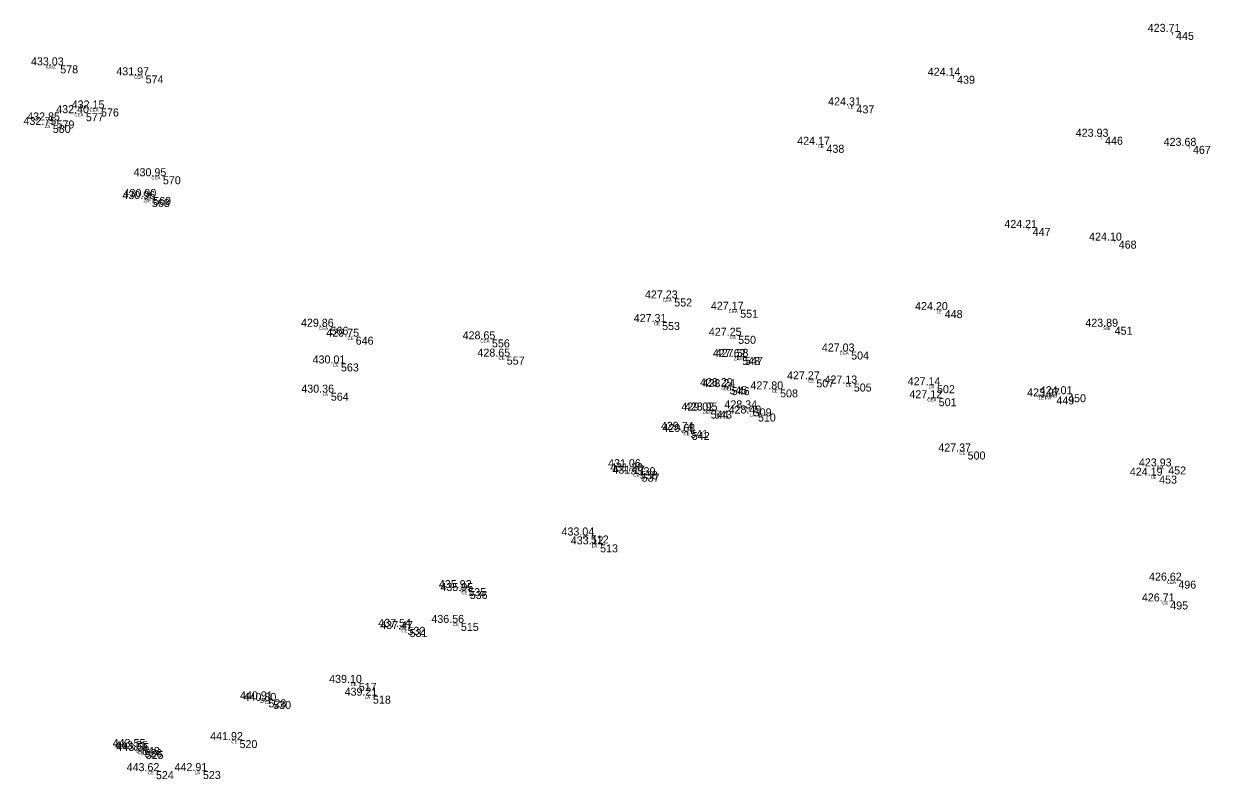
# Model space of a CAD drawing. Extents: x -639373 to -639057, y -1138651 to -1138359.
# Drawn here: x -639295.4 to -639184.2, y -1138643.1 to -1138572.3 of the extents above; entities that cross this region are included whole.
import ezdxf

# ---------------------------------------------------------------- set-up
doc = ezdxf.new("R2010")
doc.units = 0
for name, color, linetype in [('Vrstva 11', 7, 'Continuous'), ('Vrstva 12', 7, 'Continuous'), ('Vrstva 13', 7, 'Continuous'), ('Vrstva 14', 7, 'Continuous'), ('Vrstva 57', 7, 'Continuous')]:
    doc.layers.add(name, color=color, linetype=linetype)

msp = doc.modelspace()

# ---------------------------------------------------------------- linework, layer by layer
at = {"layer": 'Vrstva 11'}
for p, q in [((-639187.67, -1138573.11), (-639187.67, -1138573.11)), ((-639292.26, -1138576.25), (-639292.26, -1138576.25)), ((-639284.26, -1138577.18), (-639284.26, -1138577.18)), ((-639208.2, -1138577.22), (-639208.2, -1138577.22)), ((-639217.63, -1138580), (-639217.63, -1138580)), ((-639289.86, -1138580.73), (-639289.86, -1138580.73)), ((-639288.44, -1138580.29), (-639288.44, -1138580.29)), ((-639292.96, -1138581.83), (-639292.96, -1138581.83)), ((-639292.61, -1138581.41), (-639292.61, -1138581.41)), ((-639194.33, -1138582.94), (-639194.33, -1138582.94)), ((-639220.44, -1138583.69), (-639220.44, -1138583.69)), ((-639186.09, -1138583.79), (-639186.09, -1138583.79)), ((-639282.64, -1138586.64), (-639282.64, -1138586.64)), ((-639283.67, -1138588.77), (-639283.67, -1138588.77)), ((-639283.55, -1138588.58), (-639283.55, -1138588.58)), ((-639201.11, -1138591.48), (-639201.11, -1138591.48)), ((-639193.05, -1138592.67), (-639193.05, -1138592.67)), ((-639234.71, -1138598.09), (-639234.71, -1138598.09)), ((-639228.53, -1138599.15), (-639228.53, -1138599.15)), ((-639209.36, -1138599.18), (-639209.36, -1138599.18)), ((-639266.93, -1138600.74), (-639266.93, -1138600.74)), ((-639235.85, -1138600.3), (-639235.85, -1138600.3)), ((-639193.43, -1138600.74), (-639193.43, -1138600.74)), ((-639264.57, -1138601.67), (-639264.57, -1138601.67)), ((-639251.8, -1138601.92), (-639251.8, -1138601.92)), ((-639228.72, -1138601.59), (-639228.72, -1138601.59)), ((-639218.13, -1138603.06), (-639218.13, -1138603.06)), ((-639265.95, -1138604.18), (-639265.95, -1138604.18)), ((-639250.41, -1138603.54), (-639250.41, -1138603.54)), ((-639228.34, -1138603.58), (-639228.34, -1138603.58)), ((-639228.08, -1138603.56), (-639228.08, -1138603.56)), ((-639221.39, -1138605.67), (-639221.39, -1138605.67)), ((-639229.54, -1138606.31), (-639229.54, -1138606.31)), ((-639229.32, -1138606.4), (-639229.32, -1138606.4)), ((-639224.79, -1138606.61), (-639224.79, -1138606.61)), ((-639217.88, -1138606.06), (-639217.88, -1138606.06)), ((-639210.08, -1138606.22), (-639210.08, -1138606.22)), ((-639266.9, -1138606.92), (-639266.9, -1138606.92)), ((-639209.92, -1138607.44), (-639209.92, -1138607.44)), ((-639198.89, -1138607.27), (-639198.89, -1138607.27)), ((-639197.79, -1138607.06), (-639197.79, -1138607.06)), ((-639231.29, -1138608.59), (-639231.29, -1138608.59)), ((-639230.97, -1138608.59), (-639230.97, -1138608.59)), ((-639227.26, -1138608.39), (-639227.26, -1138608.39)), ((-639226.87, -1138608.87), (-639226.87, -1138608.87)), ((-639233.21, -1138610.4), (-639233.21, -1138610.4)), ((-639233.07, -1138610.6), (-639233.07, -1138610.6)), ((-639207.21, -1138612.43), (-639207.21, -1138612.43)), ((-639238.14, -1138613.9), (-639238.14, -1138613.9)), ((-639237.93, -1138614.28), (-639237.93, -1138614.28)), ((-639237.77, -1138614.51), (-639237.77, -1138614.51)), ((-639188.41, -1138613.83), (-639188.41, -1138613.83)), ((-639189.26, -1138614.69), (-639189.26, -1138614.69)), ((-639242.53, -1138620.3), (-639242.53, -1138620.3)), ((-639241.66, -1138621.13), (-639241.66, -1138621.13)), ((-639187.46, -1138624.53), (-639187.46, -1138624.53)), ((-639254.02, -1138625.23), (-639254.02, -1138625.23)), ((-639253.88, -1138625.5), (-639253.88, -1138625.5)), ((-639188.22, -1138626.48), (-639188.22, -1138626.48)), ((-639259.71, -1138628.86), (-639259.71, -1138628.86)), ((-639259.52, -1138629.07), (-639259.52, -1138629.07)), ((-639254.71, -1138628.49), (-639254.71, -1138628.49)), ((-639264.28, -1138634.11), (-639264.28, -1138634.11)), ((-639272.75, -1138635.65), (-639272.75, -1138635.65)), ((-639262.95, -1138635.31), (-639262.95, -1138635.31)), ((-639272.3, -1138635.8), (-639272.3, -1138635.8)), ((-639284.6, -1138640.12), (-639284.6, -1138640.12)), ((-639275.46, -1138639.47), (-639275.46, -1138639.47)), ((-639284.38, -1138640.33), (-639284.38, -1138640.33)), ((-639284.25, -1138640.49), (-639284.25, -1138640.49)), ((-639283.29, -1138642.38), (-639283.29, -1138642.38)), ((-639278.89, -1138642.37), (-639278.89, -1138642.37))]:
    msp.add_line(p, q, dxfattribs=at)

# ---------------------------------------------------------------- texts
at = {"layer": 'Vrstva 12'}
for s, p in [('433.03 ', (-639294.73, -1138576.25)), ('431.97 ', (-639286.73, -1138577.18)), ('432.40 ', (-639292.36, -1138580.73)), ('432.15 ', (-639290.91, -1138580.29)), ('432.75 ', (-639295.43, -1138581.83)), ('432.85 ', (-639295.08, -1138581.41)), ('430.95 ', (-639285.11, -1138586.64)), ('430.90 ', (-639286.05, -1138588.58)), ('430.96 ', (-639286.16, -1138588.77)), ('427.23 ', (-639237.18, -1138598.09)), ('427.17 ', (-639231, -1138599.15)), ('429.86 ', (-639269.42, -1138600.74)), ('427.31 ', (-639238.23, -1138600.3)), ('429.75 ', (-639267.04, -1138601.67)), ('428.65 ', (-639254.27, -1138601.92)), ('427.25 ', (-639231.19, -1138601.59)), ('427.03 ', (-639220.6, -1138603.06)), ('430.01 ', (-639268.33, -1138604.18)), ('428.65 ', (-639252.88, -1138603.54)), ('427.62 ', (-639230.81, -1138603.58)), ('427.58 ', (-639230.55, -1138603.56)), ('428.29 ', (-639232.01, -1138606.31)), ('428.24 ', (-639231.79, -1138606.4)), ('427.27 ', (-639223.86, -1138605.67)), ('427.13 ', (-639220.35, -1138606.06)), ('427.14 ', (-639212.55, -1138606.22)), ('430.36 ', (-639269.39, -1138606.92)), ('427.80 ', (-639227.29, -1138606.61)), ('427.12 ', (-639212.39, -1138607.44)), ('423.97 ', (-639201.36, -1138607.27)), ('424.01 ', (-639200.17, -1138607.06)), ('429.02 ', (-639233.76, -1138608.59)), ('428.95 ', (-639233.44, -1138608.59)), ('428.34 ', (-639229.73, -1138608.39)), ('428.49 ', (-639229.34, -1138608.87)), ('429.74 ', (-639235.68, -1138610.4)), ('429.68 ', (-639235.54, -1138610.6)), ('427.37 ', (-639209.68, -1138612.43)), ('431.06 ', (-639240.63, -1138613.9)), ('431.20 ', (-639240.43, -1138614.28)), ('423.93 ', (-639190.88, -1138613.83)), ('431.17 ', (-639240.24, -1138614.51)), ('424.19 ', (-639191.73, -1138614.69)), ('433.04 ', (-639245, -1138620.3)), ('433.12 ', (-639244.13, -1138621.13)), ('435.92 ', (-639256.49, -1138625.23)), ('426.62 ', (-639189.93, -1138624.53)), ('435.95 ', (-639256.35, -1138625.5)), ('426.71 ', (-639190.6, -1138626.48)), ('436.56 ', (-639257.2, -1138628.49)), ('437.54 ', (-639262.18, -1138628.86)), ('437.47 ', (-639261.99, -1138629.07)), ('439.10 ', (-639266.78, -1138634.11)), ('439.21 ', (-639265.33, -1138635.31)), ('440.91 ', (-639275.13, -1138635.65)), ('440.80 ', (-639274.8, -1138635.8)), ('441.92 ', (-639277.93, -1138639.47)), ('443.55 ', (-639287.07, -1138640.12)), ('443.55 ', (-639286.85, -1138640.33)), ('443.55 ', (-639286.72, -1138640.49)), ('443.62 ', (-639285.76, -1138642.38)), ('442.91 ', (-639281.27, -1138642.37))]:
    msp.add_text(s, height=0.75, dxfattribs=at).set_placement(p)
at = {"layer": 'Vrstva 13'}
for s, p in [(' 445', (-639187.67, -1138573.86)), (' 578', (-639292.26, -1138577)), (' 574', (-639284.26, -1138577.93)), (' 439', (-639208.2, -1138577.97)), (' 437', (-639217.63, -1138580.75)), (' 577', (-639289.86, -1138581.48)), (' 576', (-639288.44, -1138581.04)), (' 580', (-639292.96, -1138582.58)), (' 579', (-639292.61, -1138582.16)), (' 446', (-639194.33, -1138583.69)), (' 438', (-639220.44, -1138584.44)), (' 467', (-639186.09, -1138584.54)), (' 570', (-639282.64, -1138587.39)), (' 568', (-639283.67, -1138589.52)), (' 569', (-639283.55, -1138589.33)), (' 447', (-639201.11, -1138592.23)), (' 468', (-639193.05, -1138593.42)), (' 552', (-639234.71, -1138598.84)), (' 551', (-639228.53, -1138599.9)), (' 448', (-639209.36, -1138599.93)), (' 566', (-639266.93, -1138601.49)), (' 553', (-639235.85, -1138601.05)), (' 451', (-639193.43, -1138601.49)), (' 646', (-639264.57, -1138602.42)), (' 556', (-639251.8, -1138602.67)), (' 550', (-639228.72, -1138602.34)), (' 504', (-639218.13, -1138603.81)), (' 563', (-639265.95, -1138604.93)), (' 557', (-639250.41, -1138604.29)), (' 548', (-639228.34, -1138604.33)), (' 547', (-639228.08, -1138604.31)), (' 507', (-639221.39, -1138606.42)), (' 545', (-639229.54, -1138607.06)), (' 546', (-639229.32, -1138607.15)), (' 508', (-639224.79, -1138607.36)), (' 505', (-639217.88, -1138606.81)), (' 502', (-639210.08, -1138606.97)), (' 564', (-639266.9, -1138607.67)), (' 501', (-639209.92, -1138608.19)), (' 449', (-639198.89, -1138608.02)), (' 450', (-639197.79, -1138607.81)), (' 544', (-639231.29, -1138609.34)), (' 543', (-639230.97, -1138609.34)), (' 509', (-639227.26, -1138609.14)), (' 510', (-639226.87, -1138609.62)), (' 541', (-639233.21, -1138611.15)), (' 542', (-639233.07, -1138611.35)), (' 500', (-639207.21, -1138613.18)), (' 539', (-639238.14, -1138614.65)), (' 538', (-639237.93, -1138615.03)), (' 537', (-639237.77, -1138615.26)), (' 452', (-639188.41, -1138614.58)), (' 453', (-639189.26, -1138615.44)), (' 512', (-639242.53, -1138621.05)), (' 513', (-639241.66, -1138621.88)), (' 496', (-639187.46, -1138625.28)), (' 535', (-639254.02, -1138625.98)), (' 536', (-639253.88, -1138626.25)), (' 495', (-639188.22, -1138627.23)), (' 532', (-639259.71, -1138629.61)), (' 531', (-639259.52, -1138629.82)), (' 515', (-639254.71, -1138629.24)), (' 517', (-639264.28, -1138634.86)), (' 528', (-639272.75, -1138636.4)), (' 518', (-639262.95, -1138636.06)), (' 530', (-639272.3, -1138636.55)), (' 648', (-639284.6, -1138640.87)), (' 520', (-639275.46, -1138640.22)), (' 526', (-639284.38, -1138641.08)), (' 525', (-639284.25, -1138641.24)), (' 524', (-639283.29, -1138643.13)), (' 523', (-639278.89, -1138643.12))]:
    msp.add_text(s, height=0.75, dxfattribs=at).set_placement(p)
at = {"layer": 'Vrstva 14'}
for s, p in [('423.71 ', (-639190.05, -1138573.11)), ('424.14 ', (-639210.67, -1138577.22)), ('424.31 ', (-639220.01, -1138580)), ('423.93 ', (-639196.8, -1138582.94)), ('424.17 ', (-639222.91, -1138583.69)), ('423.68 ', (-639188.56, -1138583.79)), ('424.21 ', (-639203.49, -1138591.48)), ('424.10 ', (-639195.55, -1138592.67)), ('424.20 ', (-639211.86, -1138599.18)), ('423.89 ', (-639195.9, -1138600.74))]:
    msp.add_text(s, height=0.75, dxfattribs=at).set_placement(p)
at = {"layer": 'Vrstva 57'}
for s, p in [('T', (-639187.87, -1138573.41)), ('KRIZ', (-639293.35, -1138576.55)), ('CEA', (-639285.06, -1138577.48)), ('T', (-639208.4, -1138577.52)), ('LE', (-639218.12, -1138580.3)), ('CEA', (-639290.66, -1138581.03)), ('CEA', (-639289.24, -1138580.59)), ('ZA', (-639293.46, -1138582.13)), ('CE', (-639293.1, -1138581.71)), ('T', (-639194.53, -1138583.24)), ('LE', (-639220.93, -1138583.99)), ('T', (-639186.29, -1138584.09)), ('CEA', (-639283.44, -1138586.94)), ('ZA', (-639284.17, -1138589.07)), ('CE', (-639284.04, -1138588.88)), ('T', (-639201.31, -1138591.78)), ('T', (-639193.25, -1138592.97)), ('CEA', (-639235.51, -1138598.39)), ('CEA', (-639229.33, -1138599.45)), ('LE', (-639209.85, -1138599.48)), ('CEA', (-639267.73, -1138601.04)), ('CE', (-639236.34, -1138600.6)), ('SIB', (-639194.22, -1138601.04)), ('CE', (-639265.06, -1138601.97)), ('CEA', (-639252.6, -1138602.22)), ('CE', (-639229.21, -1138601.89)), ('CEA', (-639218.93, -1138603.36)), ('CE', (-639266.44, -1138604.48)), ('CE', (-639250.9, -1138603.84)), ('ZA', (-639228.84, -1138603.88)), ('CE', (-639228.57, -1138603.86)), ('CE', (-639221.88, -1138605.97)), ('ZA', (-639230.04, -1138606.61)), ('CE', (-639229.81, -1138606.7)), ('CE', (-639225.28, -1138606.91)), ('CE', (-639218.37, -1138606.36)), ('LA', (-639210.58, -1138606.52)), ('LA', (-639267.4, -1138607.22)), ('CEA', (-639210.72, -1138607.74)), ('PA SIA SIB', (-639200.68, -1138607.36)), ('LE PA', (-639200.29, -1138607.57)), ('ZA', (-639231.79, -1138608.89)), ('CE', (-639231.46, -1138608.89)), ('CE', (-639227.75, -1138608.69)), ('LA', (-639227.37, -1138609.17)), ('ZA', (-639233.71, -1138610.7)), ('CE', (-639233.56, -1138610.9)), ('CE', (-639207.7, -1138612.73)), ('HR', (-639238.63, -1138614.2)), ('ZA', (-639238.43, -1138614.58)), ('CE', (-639238.26, -1138614.81)), ('SIA', (-639189.21, -1138614.13)), ('LE', (-639189.75, -1138614.99)), ('CE', (-639243.02, -1138620.6)), ('LA', (-639242.16, -1138621.43)), ('CEA', (-639188.26, -1138624.83)), ('ZA', (-639254.52, -1138625.53)), ('CE', (-639254.37, -1138625.8)), ('CE', (-639188.71, -1138626.78)), ('ZA', (-639260.21, -1138629.16)), ('CE', (-639260.01, -1138629.37)), ('CE', (-639255.2, -1138628.79)), ('CE', (-639264.77, -1138634.41)), ('ZA', (-639273.25, -1138635.95)), ('LA', (-639263.45, -1138635.61)), ('CE', (-639272.79, -1138636.1)), ('LE', (-639285.09, -1138640.42)), ('CE', (-639275.95, -1138639.77)), ('ZA', (-639284.88, -1138640.63)), ('CE', (-639284.74, -1138640.79)), ('CE', (-639283.78, -1138642.68)), ('LA', (-639279.39, -1138642.67))]:
    msp.add_text(s, height=0.3, dxfattribs=at).set_placement(p)

doc.saveas('drawing.dxf')
